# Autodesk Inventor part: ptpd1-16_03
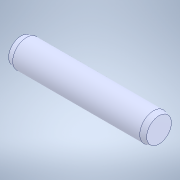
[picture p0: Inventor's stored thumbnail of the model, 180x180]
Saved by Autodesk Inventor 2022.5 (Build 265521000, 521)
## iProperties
Created: 2023-04
Part Number: ptpd1-16_03
Material: Generic
Document SubType Name: Modeling
Designer: ImaoCorp
Density: 1 g/cm^3
Appearance: Default
Author: ImaoCorp
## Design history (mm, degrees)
feature "ptpd1-16_03"
node "ソリッド1"
